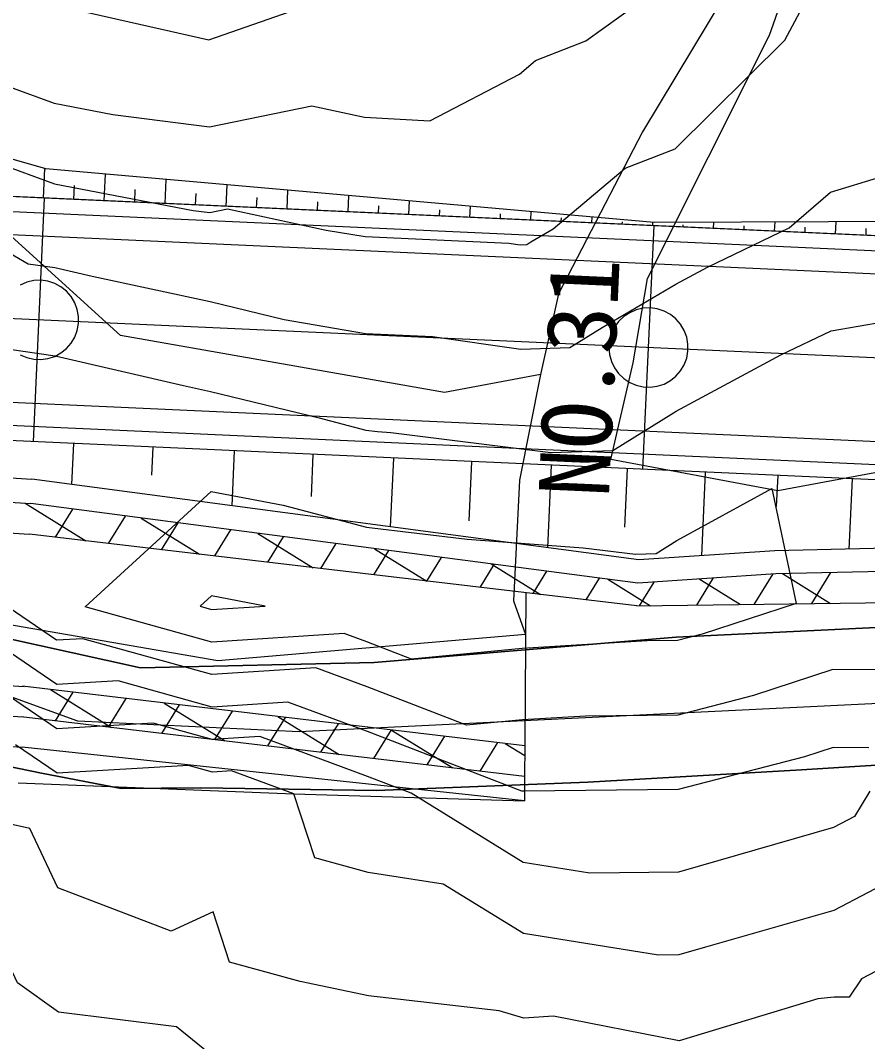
# Model space of a CAD drawing. Extents: x 42655 to 43811, y -141820 to -141156.
# Drawn here: x 43447.72 to 43475.49, y -141364.6 to -141331.1 of the extents above; entities that cross this region are included whole.
import ezdxf

# ---------------------------------------------------------------- set-up
doc = ezdxf.new("R2010")
doc.units = 0
for name, color, linetype in [('D-BMK-HTXT_1', 7, 'Continuous'), ('D-BMK_1', 7, 'Continuous'), ('D-STR', 7, 'Continuous'), ('D-STR-STR4_1', 7, 'Continuous'), ('D-STR_1', 7, 'Continuous'), ('ZE_HICN', 7, 'Continuous'), ('ZE_LWCN', 7, 'Continuous'), ('地形', 7, 'Continuous'), ('現況水路ﾊｯﾁ', 7, 'Continuous')]:
    doc.layers.add(name, color=color, linetype=linetype)

msp = doc.modelspace()

# ---------------------------------------------------------------- linework, layer by layer
at = {"layer": 'D-BMK-HTXT_1'}
for p, q in [((43448.149, -141344.92), (43448.512, -141336.928)), ((43468.128, -141345.827), (43468.491, -141337.835))]:
    msp.add_line(p, q, dxfattribs=at)
for points in [[(43447.714, -141342.069), (43447.928, -141342.16), (43448.156, -141342.212), (43448.388, -141342.223), (43448.619, -141342.191), (43448.841, -141342.119), (43449.046, -141342.009), (43449.229, -141341.863), (43449.382, -141341.688), (43449.501, -141341.488), (43449.583, -141341.27), (43449.625, -141341.04), (43449.625, -141340.807), (43449.583, -141340.578), (43449.501, -141340.36), (43449.382, -141340.16), (43449.228, -141339.984), (43449.046, -141339.839), (43448.841, -141339.728), (43448.619, -141339.656), (43448.388, -141339.625), (43448.156, -141339.636), (43447.928, -141339.687), (43447.714, -141339.779)], [(43467.01, -141341.831), (43467.03, -141342.063), (43467.092, -141342.288), (43467.194, -141342.498), (43467.331, -141342.686), (43467.499, -141342.848), (43467.694, -141342.976), (43467.908, -141343.068), (43468.135, -141343.119), (43468.368, -141343.13), (43468.599, -141343.099), (43468.82, -141343.027), (43469.026, -141342.916), (43469.208, -141342.771), (43469.361, -141342.595), (43469.481, -141342.395), (43469.563, -141342.177), (43469.604, -141341.948), (43469.604, -141341.715), (43469.563, -141341.485), (43469.481, -141341.267), (43469.361, -141341.067), (43469.208, -141340.892), (43469.026, -141340.746), (43468.82, -141340.636), (43468.599, -141340.564), (43468.368, -141340.532), (43468.135, -141340.543), (43467.908, -141340.595), (43467.693, -141340.686), (43467.499, -141340.815), (43467.331, -141340.976), (43467.194, -141341.164), (43467.092, -141341.374), (43467.03, -141341.599), (43467.01, -141341.831)]]:
    msp.add_lwpolyline(points, dxfattribs=at)
at = {"layer": 'D-BMK_1'}
msp.add_lwpolyline([(43648.124, -141349.997), (43439.808, -141340.537)], dxfattribs=at)
at = {"layer": 'D-STR'}
for p, q in [((43467.993, -141348.797), (43448.093, -141346.151)), ((43447.875, -141346.939), (43449.861, -141348.169)), ((43467.959, -141349.561), (43448.056, -141346.951)), ((43449.427, -141347.13), (43448.858, -141348.05)), ((43451.154, -141347.357), (43450.597, -141348.256)), ((43451.675, -141347.425), (43453.588, -141348.61)), ((43452.881, -141347.583), (43452.337, -141348.462)), ((43454.608, -141347.81), (43454.077, -141348.668)), ((43455.5, -141347.927), (43457.316, -141349.052)), ((43467.925, -141350.308), (43448.011, -141347.95)), ((43456.335, -141348.037), (43455.816, -141348.874)), ((43458.062, -141348.263), (43457.556, -141349.08)), ((43459.789, -141348.49), (43459.296, -141349.286)), ((43459.325, -141348.429), (43461.044, -141349.493)), ((43461.516, -141348.716), (43461.036, -141349.492)), ((43463.15, -141348.93), (43464.772, -141349.935)), ((43463.243, -141348.943), (43462.775, -141349.698)), ((43464.97, -141349.169), (43464.515, -141349.904)), ((43472.386, -141349.256), (43471.766, -141350.257)), ((43472.702, -141349.245), (43474.281, -141350.223)), ((43474.281, -141349.211), (43473.649, -141350.231)), ((43466.697, -141349.396), (43466.255, -141350.11)), ((43466.975, -141349.432), (43468.38, -141350.302)), ((43468.485, -141349.525), (43468, -141350.307)), ((43470.435, -141349.39), (43469.883, -141350.282)), ((43469.974, -141349.422), (43471.33, -141350.262)), ((43464.283, -141349.877), (43464.252, -141354.895)), ((43464.252, -141354.895), (43447.784, -141352.944)), ((43448.702, -141353.053), (43450.707, -141354.295)), ((43449.439, -141353.141), (43448.86, -141354.076)), ((43451.179, -141353.347), (43450.599, -141354.282)), ((43452.919, -141353.553), (43452.339, -141354.488)), ((43452.43, -141353.495), (43454.435, -141354.737)), ((43464.246, -141355.899), (43447.739, -141353.943)), ((43454.658, -141353.759), (43454.079, -141354.694)), ((43456.158, -141353.936), (43458.163, -141355.178)), ((43456.398, -141353.965), (43455.819, -141354.9)), ((43458.138, -141354.171), (43457.558, -141355.107)), ((43459.878, -141354.377), (43459.298, -141355.313)), ((43459.885, -141354.378), (43461.89, -141355.62)), ((43461.617, -141354.583), (43461.038, -141355.519)), ((43464.241, -141356.701), (43447.78, -141354.946)), ((43463.357, -141354.789), (43462.777, -141355.725)), ((43463.613, -141354.819), (43464.25, -141355.214)), ((43464.252, -141354.895), (43464.246, -141355.899)), ((43464.246, -141355.899), (43464.241, -141356.701))]:
    msp.add_line(p, q, dxfattribs=at)
for points in [[(43398.004, -141344.053), (43428.165, -141344.263), (43439.578, -141345.606), (43448.093, -141346.151)], [(43397.238, -141344.847), (43428.129, -141345.063), (43439.542, -141346.405), (43448.056, -141346.951)], [(43398.048, -141345.583), (43428.089, -141346), (43439.496, -141347.404), (43448.011, -141347.95)], [(43400.369, -141350.615), (43427.924, -141350.997), (43439.331, -141352.401), (43447.846, -141352.947)], [(43400.882, -141351.624), (43427.891, -141351.997), (43439.298, -141353.401), (43447.813, -141353.946)], [(43400.987, -141352.623), (43427.858, -141352.996), (43439.265, -141354.4), (43447.78, -141354.946)], [(43447.64, -141356.114), (43456.677, -141356.468), (43464.241, -141356.701)]]:
    msp.add_lwpolyline(points, dxfattribs=at)
at = {"layer": 'D-STR-STR4_1'}
for p, q in [((43448.469, -141336.926), (43448.513, -141335.96)), ((43450.467, -141337.017), (43450.506, -141336.144)), ((43449.468, -141336.971), (43449.488, -141336.514)), ((43452.465, -141337.107), (43452.5, -141336.319)), ((43454.462, -141337.198), (43454.494, -141336.494)), ((43451.466, -141337.062), (43451.484, -141336.647)), ((43453.463, -141337.153), (43453.48, -141336.78)), ((43456.46, -141337.289), (43456.489, -141336.669)), ((43458.458, -141337.38), (43458.483, -141336.845)), ((43455.461, -141337.244), (43455.476, -141336.913)), ((43457.459, -141337.334), (43457.472, -141337.046)), ((43459.457, -141337.425), (43459.468, -141337.179)), ((43460.456, -141337.47), (43460.477, -141337.02)), ((43462.454, -141337.561), (43462.471, -141337.195)), ((43461.455, -141337.516), (43461.465, -141337.312)), ((43463.453, -141337.607), (43463.461, -141337.445)), ((43464.452, -141337.652), (43464.465, -141337.371)), ((43466.45, -141337.743), (43466.459, -141337.546)), ((43465.451, -141337.697), (43465.457, -141337.578)), ((43467.449, -141337.788), (43467.453, -141337.711)), ((43468.448, -141337.833), (43468.453, -141337.721)), ((43469.447, -141337.879), (43469.451, -141337.8)), ((43470.446, -141337.924), (43470.455, -141337.717)), ((43471.445, -141337.969), (43471.451, -141337.841)), ((43472.444, -141338.015), (43472.458, -141337.71)), ((43474.442, -141338.106), (43474.46, -141337.702)), ((43473.443, -141338.06), (43473.451, -141337.883)), ((43475.441, -141338.151), (43475.451, -141337.925)), ((43449.456, -141344.979), (43449.395, -141346.325)), ((43452.062, -141345.097), (43452.02, -141346.02)), ((43454.727, -141345.218), (43454.645, -141347.023)), ((43457.308, -141345.336), (43457.245, -141346.714)), ((43459.948, -141345.456), (43459.845, -141347.714)), ((43462.504, -141345.572), (43462.416, -141347.518)), ((43465.12, -141345.69), (43464.997, -141348.399)), ((43467.614, -141345.804), (43467.526, -141347.725)), ((43470.166, -141345.92), (43470.042, -141348.663)), ((43472.545, -141346.028), (43472.499, -141347.041)), ((43474.983, -141346.138), (43474.878, -141348.447))]:
    msp.add_line(p, q, dxfattribs=at)
for points in [[(43488.52, -141337.648), (43468.496, -141337.725), (43448.555, -141335.972), (43440.125, -141333.553)], [(43488.47, -141338.743), (43468.491, -141337.835), (43448.512, -141336.928), (43439.99, -141336.541)]]:
    msp.add_lwpolyline(points, dxfattribs=at)
at = {"layer": 'D-STR_1'}
msp.add_line((43467.925, -141350.308), (43507.45, -141349.776), dxfattribs=at)
for points in [[(43518.44, -141340.104), (43439.99, -141336.541)], [(43648.283, -141346.5), (43439.967, -141337.04)], [(43648.249, -141347.25), (43439.933, -141337.79)], [(43647.999, -141352.744), (43439.683, -141343.284)], [(43647.965, -141353.493), (43439.649, -141344.033)], [(43647.943, -141353.993), (43439.627, -141344.533)], [(43507.509, -141348.979), (43494.163, -141347.988), (43472.453, -141348.505), (43467.993, -141348.797)], [(43507.45, -141349.776), (43494.128, -141348.787), (43472.486, -141349.249), (43467.959, -141349.561)]]:
    msp.add_lwpolyline(points, dxfattribs=at)
at = {"layer": 'ZE_HICN'}
for points in [[(43434.881, -141330.296), (43438.633, -141331.413), (43439.497, -141331.899), (43442.12, -141333.839), (43443.735, -141334.524), (43446.976, -141335.782), (43448.833, -141336.457), (43453.377, -141337.332), (43453.925, -141337.402), (43454.509, -141337.283), (43457.744, -141337.975), (43459.017, -141338.191), (43463.729, -141338.404), (43464.107, -141338.459), (43464.316, -141338.452), (43464.455, -141338.365), (43465.179, -141337.94), (43467.545, -141335.945), (43469.18, -141335.307), (43472.777, -141331.741), (43473.36, -141330.665)], [(43475.571, -141356.379), (43475.063, -141357.218), (43474.373, -141357.579), (43473.088, -141357.949), (43469.292, -141359.042), (43466.391, -141359.071), (43464.202, -141358.72), (43460.525, -141356.45), (43459.101, -141355.898), (43455.564, -141354.588), (43454.007, -141354.69), (43452.075, -141354.153), (43448.917, -141354.339), (43444.761, -141351.507)]]:
    msp.add_lwpolyline(points, dxfattribs=at)
at = {"layer": 'ZE_LWCN'}
for points in [[(43438.622, -141329.078), (43443.6, -141331.879), (43443.676, -141331.936), (43443.723, -141331.956), (43443.818, -141331.992), (43448.82, -141333.812), (43450.753, -141334.184), (43453.912, -141334.588), (43457.273, -141333.903), (43458.999, -141334.272), (43461.145, -141334.396), (43464.08, -141332.859), (43464.604, -141332.418), (43466.256, -141331.772), (43469.153, -141329.675)], [(43449.688, -141330.782), (43453.899, -141331.733), (43457.787, -141330.367)], [(43446.166, -141338.03), (43447.972, -141339.079), (43448.846, -141339.203), (43450.067, -141339.489), (43453.939, -141340.323), (43456.363, -141340.915), (43459.032, -141341.368), (43461.224, -141341.467), (43464.123, -141341.882), (43465.73, -141341.831), (43466.791, -141341.168), (43469.201, -141339.753), (43470.249, -141339.189), (43472.923, -141337.903), (43474.275, -141336.737), (43477.582, -141335.73)], [(43454.056, -141365.114), (43452.84, -141364.117), (43448.961, -141363.631), (43447.622, -141362.674), (43446.257, -141359.771), (43443.852, -141359.239), (43439.294, -141357.203), (43438.753, -141356.959), (43437.983, -141356.557), (43437.728, -141355.325), (43435.215, -141350.407), (43434.181, -141349.746), (43433.63, -141349.408), (43431.92, -141348.358), (43428.533, -141347.621), (43424.624, -141344.294), (43423.41, -141340.36), (43420.871, -141341.231), (43418.331, -141342.102), (43417.723, -141343.582), (43417.384, -141344.329), (43417.713, -141349.698), (43413.28, -141350.088)], [(43445.856, -141341.667), (43448.859, -141342.097), (43453.06, -141343.079), (43453.953, -141343.271), (43457.507, -141344.139), (43459.047, -141344.545), (43459.428, -141344.59), (43459.864, -141344.622), (43465.107, -141345.275), (43467.144, -141345.211), (43469.128, -141343.971), (43469.221, -141343.917), (43472.652, -141342.071), (43474.296, -141341.28), (43476.954, -141340.826)], [(43458.328, -141351.207), (43453.992, -141351.491), (43449.841, -141350.338), (43453.969, -141346.552), (43456.329, -141347.001), (43459.062, -141347.721), (43462.369, -141348.118), (43466.164, -141348.397), (43467.888, -141348.611), (43468.558, -141348.59), (43469.241, -141348.164), (43472.349, -141346.457), (43473.146, -141350.228), (43470.073, -141351.232), (43469.256, -141351.444), (43468.263, -141351.454), (43464.169, -141351.699), (43460.539, -141352.051), (43459.08, -141351.486), (43458.328, -141351.207)], [(43453.987, -141350.425), (43455.741, -141350.31), (43453.985, -141349.976), (43453.61, -141350.32), (43453.987, -141350.425)], [(43475.534, -141354.959), (43474.361, -141354.953), (43473.428, -141355.257), (43469.279, -141356.335), (43464.232, -141356.383), (43464.191, -141356.386), (43464.155, -141356.389), (43459.094, -141354.427), (43456.485, -141353.461), (43454.002, -141353.623), (43450.92, -141352.767), (43448.91, -141352.886), (43445.204, -141350.36)], [(43477.615, -141352.413), (43474.349, -141352.395), (43471.75, -141353.245), (43469.268, -141353.89), (43466.247, -141353.919), (43464.18, -141354.043), (43462.347, -141354.22), (43459.087, -141352.956), (43457.407, -141352.334), (43453.997, -141352.557), (43449.765, -141351.382), (43448.904, -141351.432), (43447.315, -141350.35)], [(43476.642, -141359.113), (43474.386, -141360.294), (43470.181, -141361.504), (43469.305, -141361.757), (43468.636, -141361.763), (43464.214, -141361.055), (43461.582, -141359.43), (43459.116, -141359.056), (43457.371, -141358.576), (43456.677, -141356.468), (43454.642, -141355.715), (43454.012, -141355.756), (43453.23, -141355.539), (43448.924, -141355.793), (43447.557, -141354.861)], [(43478.221, -141361.007), (43475.289, -141362.543), (43474.894, -141363.143), (43474.4, -141363.146), (43473.866, -141363.196), (43469.318, -141364.578), (43465.193, -141363.761), (43464.227, -141363.835), (43463.409, -141363.587), (43459.135, -141363.098), (43456.888, -141362.63), (43454.576, -141361.994), (43454.034, -141360.348), (43452.656, -141360.977), (43448.942, -141359.556), (43448.025, -141357.608), (43443.84, -141356.682)]]:
    msp.add_lwpolyline(points, dxfattribs=at)
at = {"layer": '地形'}
for points in [[(43472.544, -141316.076), (43472.249, -141324.334), (43471.363, -141329.348), (43468.116, -141334.755), (43465.362, -141340.064), (43464.771, -141342.718), (43461.623, -141343.308), (43450.996, -141341.44), (43438.795, -141330.331), (43439.877, -141328.464), (43445.683, -141321.779), (43448.733, -141319.321), (43451.291, -141315.487), (43472.544, -141316.076)], [(43467.073, -141345.502), (43467.808, -141342.337), (43468.282, -141339.565), (43472.274, -141331.587), (43472.68, -141330.437), (43474.44, -141323.947), (43475.319, -141316.982), (43477.349, -141316.103)], [(43464.771, -141342.718), (43464.081, -141346.182), (43463.888, -141350.135), (43464.274, -141351.244), (43454.189, -141352.112), (43446.661, -141350.811), (43438.505, -141345.314), (43434.5, -141341.891), (43441.98, -141333.261)], [(43553.691, -141354.812), (43550.208, -141356.373), (43546.065, -141357.213), (43542.041, -141357.333), (43538.86, -141357.323), (43534.355, -141356.365), (43529.057, -141354.989), (43522.883, -141353.53), (43517.334, -141352.446), (43510.743, -141351.321), (43504.861, -141350.612), (43498.353, -141350.279), (43495.141, -141350.071), (43486.185, -141350.513), (43469.214, -141351.337), (43459.314, -141352.162), (43451.654, -141352.339), (43446.055, -141351.102), (43441.223, -141348.158), (43435.118, -141343.288), (43425.795, -141335.807), (43423.686, -141334.529), (43420.559, -141333.955), (43416.507, -141334.688)], [(43647.722, -141358.843), (43628.878, -141354.259), (43624.278, -141352.34), (43610.656, -141352.746), (43600.049, -141357.9), (43584.108, -141344.001), (43579.575, -141340.103), (43575.981, -141339.003), (43571.17, -141339.119), (43567.866, -141341.494), (43559.565, -141353.262), (43554.745, -141358.368), (43544.775, -141360.801), (43537.008, -141359.816), (43506.675, -141352.748), (43493.73, -141352.632), (43456.856, -141354.434), (43449.599, -141354.085), (43443.512, -141351.884), (43435.686, -141346.669), (43422.979, -141336.46), (43420.429, -141335.881), (43409.299, -141338.603)], [(43416.471, -141339.059), (43419.923, -141338.403), (43421.96, -141338.817), (43423.894, -141339.748), (43427.45, -141343.06), (43432.11, -141347.062), (43435.183, -141349.166), (43438.264, -141351.359), (43441.238, -141353.396), (43443.588, -141354.331), (43445.483, -141355.194), (43448.409, -141355.793), (43451.023, -141356.296), (43453.637, -141356.272), (43459.396, -141356.357), (43466.324, -141356.094), (43473.328, -141355.68), (43481.912, -141355.153)], [(43479.854, -141345.177), (43472.545, -141346.529), (43467.073, -141345.502)]]:
    msp.add_lwpolyline(points, dxfattribs=at)
at = {"layer": '現況水路ﾊｯﾁ'}
for points in [[(43416.507, -141334.688), (43420.559, -141333.955), (43423.686, -141334.529), (43425.795, -141335.807), (43435.118, -141343.288), (43441.223, -141348.158), (43446.055, -141351.102), (43451.654, -141352.339), (43459.314, -141352.162), (43469.214, -141351.337), (43486.185, -141350.513), (43495.141, -141350.071), (43498.353, -141350.279), (43504.861, -141350.612), (43510.743, -141351.321), (43517.334, -141352.446), (43522.883, -141353.53), (43529.057, -141354.989), (43534.355, -141356.365), (43538.86, -141357.323), (43542.041, -141357.333), (43546.065, -141357.213), (43550.208, -141356.373), (43553.691, -141354.812)], [(43481.912, -141355.153), (43473.328, -141355.68), (43466.324, -141356.094), (43459.396, -141356.357), (43453.637, -141356.272), (43451.023, -141356.296), (43448.409, -141355.793), (43445.483, -141355.194), (43443.588, -141354.331), (43441.238, -141353.396), (43438.264, -141351.359), (43435.183, -141349.166), (43432.11, -141347.062), (43427.45, -141343.06), (43423.894, -141339.748), (43421.96, -141338.817), (43419.923, -141338.403), (43416.471, -141339.059)]]:
    msp.add_lwpolyline(points, dxfattribs=at)

# ---------------------------------------------------------------- texts
at = {"layer": 'D-BMK-HTXT_1'}
msp.add_text('NO.31', height=2.3065, rotation=87.3991, dxfattribs=at).set_placement((43467.009, -141346.777))

doc.saveas('drawing.dxf')
